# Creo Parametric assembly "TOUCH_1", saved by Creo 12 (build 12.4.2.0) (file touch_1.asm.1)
Units: Custom; MM, KILOGRAM, SECS

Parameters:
  PTC_WM_ITERATION = "0"
  PTC_WM_VERSION = "-.0"
  PTC_WM_LIFECYCLE_STATE = "In Work"
  PTC_WM_LIFECYCLE = "MO_CADDocument"
  PTC_WM_CREATED_BY = "Maximilian Roepper (Z0017RMS: MO)"
  PTC_WM_CREATED_ON = "18-Sep-26 11:36:42 AM"
  PTC_WM_MODIFIED_BY = "Maximilian Roepper (Z0017RMS: MO)"
  PTC_WM_MODIFIED_ON = "18-Sep-26 11:36:46 AM"
  PDMLINKNUMBER = "PDM000071455106"
  PTC_WM_NUMBER = "PDM000071455106"

Other parameters: WEIGHT, WEIGHT_FACTOR, WEIGHT_ADD, MC_ERRORS, SUPPLIER

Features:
  1. coordinate system
  2. imported feature
  3. component "LINE_SILK001_1"
  4. component "LINE_SILK002_1"
  5. component "SHAPESTRING109_1"

Other named items: DRW_VIEW_ORG, ROUGH-GROB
